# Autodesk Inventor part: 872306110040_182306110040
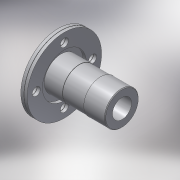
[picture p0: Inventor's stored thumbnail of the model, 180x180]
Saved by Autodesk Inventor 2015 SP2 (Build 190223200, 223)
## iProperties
Created: 2017-02
Part Number: 872306110040_182306110040
Material: PVC-Piping
Description: PLASSON FLANGE ADAPTOR WITH METAL FLANGE 110-4"
Document SubType Name: Modeling
Designer: KIM
Mass: 92.6774 g
Surface Area: 199.44 cm^2
Volume: 66.1981 cm^3
Density: 1.4 g/cm^3
Appearance: Smooth - White
Author: Кирилл
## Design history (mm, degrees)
derived "872306.ipt"
feature "Solid1::872306.ipt"
tag "TaggingFeature1"
body "Solid1"
other parameters: "d73" = 21, "d74" = 90 deg, "d75" = 0.3, "d77" = 18, "d80" = 0, "d82" = 360 deg, "d96" = 0.3, "d99" = 360 deg, "d104" = 2.2, "d107" = 143, "d108" = 5.25, "d116" = 107.8, "d120" = 5.5, "S_" = 18
